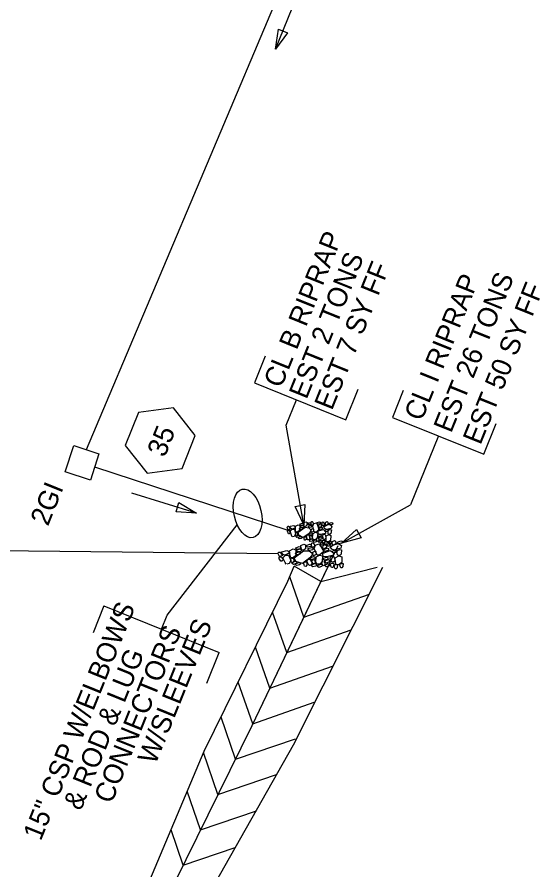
# Model space of a CAD drawing. Extents: x 2384780 to 2405432, y 547869 to 573706.
# Drawn here: x 2395530.7 to 2395662.9, y 556614.5 to 556830.4 of the extents above; entities that cross this region are included whole.
import ezdxf

# ---------------------------------------------------------------- set-up
doc = ezdxf.new("R2010")
doc.units = 0
for name, color, linetype in [('Old_Level_1', 7, 'Continuous'), ('Old_Level_10', 7, 'Continuous'), ('Old_Level_18', 7, 'Continuous'), ('Old_Level_20', 7, 'Continuous'), ('Old_Level_5', 7, 'Continuous'), ('Old_Level_9', 7, 'Continuous'), ('Prop Drainage Box Number Symbol CELL', 7, 'Continuous')]:
    doc.layers.add(name, color=color, linetype=linetype)

# ---------------------------------------------------------------- blocks, each defined once
blk = doc.blocks.new('BUBBLE')
at = {"layer": 'Old_Level_10'}
blk.add_ellipse((0, 0), major_axis=(192.5, 153.8), ratio=0.548538, dxfattribs=at)

msp = doc.modelspace()

# ---------------------------------------------------------------- linework, layer by layer
at = {"layer": 'Old_Level_1'}
for p, q in [((2395548.19, 556720.95), (2395656.03, 556976.14)), ((2395550.28, 556716.57), (2395599.15, 556700.58)), ((2395304.76, 556697.48), (2395596.66, 556694.68))]:
    msp.add_line(p, q, dxfattribs=at)
for points in [[(2395603.28, 556701.46), (2395603.18, 556701.86), (2395603.2, 556702.46), (2395603.72, 556702.67), (2395604.02, 556702.51), (2395603.9, 556701.65), (2395603.57, 556701.44), (2395603.28, 556701.46)], [(2395605.34, 556702.73), (2395605.52, 556702.54), (2395605.62, 556702.12), (2395605.41, 556701.83), (2395605.09, 556701.83), (2395605.04, 556702.44), (2395605.15, 556702.73), (2395605.34, 556702.73)], [(2395607.45, 556702.37), (2395607.26, 556702.14), (2395606.77, 556702.05), (2395606.54, 556702.27), (2395606.59, 556702.45), (2395607.15, 556702.63), (2395607.33, 556702.56), (2395607.45, 556702.37)], [(2395608.08, 556702.65), (2395608.29, 556702.37), (2395608.35, 556701.93), (2395608.16, 556701.66), (2395607.86, 556701.67), (2395607.81, 556702.27), (2395607.88, 556702.57), (2395608.08, 556702.65)], [(2395608.77, 556701.82), (2395608.67, 556702.12), (2395608.8, 556702.53), (2395609.14, 556702.7), (2395609.32, 556702.58), (2395609.3, 556701.98), (2395608.96, 556701.81), (2395608.77, 556701.82)], [(2395599.45, 556701.57), (2395599.53, 556701.34), (2395599.74, 556700.8), (2395599.43, 556700.67), (2395599.24, 556700.67), (2395599.02, 556701.24), (2395599.15, 556701.57), (2395599.45, 556701.57)], [(2395599.55, 556700.55), (2395599.61, 556700.33), (2395599.82, 556699.83), (2395599.52, 556699.65), (2395599.34, 556699.66), (2395599.08, 556700.28), (2395599.25, 556700.57), (2395599.55, 556700.55)], [(2395601.05, 556701.17), (2395600.74, 556701), (2395600.14, 556700.79), (2395599.73, 556701.15), (2395599.74, 556701.55), (2395600.65, 556701.72), (2395600.94, 556701.51), (2395601.05, 556701.17)], [(2395600.22, 556698.89), (2395600.05, 556699.3), (2395599.78, 556700.29), (2395600.29, 556700.8), (2395600.82, 556700.73), (2395601.07, 556699.53), (2395600.75, 556698.97), (2395600.34, 556698.88)], [(2395601.16, 556700.09), (2395601.06, 556700.58), (2395601.1, 556701.59), (2395601.79, 556701.92), (2395602.19, 556701.71), (2395602.07, 556700.47), (2395601.64, 556700.08), (2395601.16, 556700.09)], [(2395604.99, 556700.34), (2395604.48, 556699.65), (2395603.04, 556698.68), (2395601.97, 556699.24), (2395601.76, 556700.04), (2395603.52, 556701.3), (2395604.49, 556701.14), (2395605.13, 556700.44)], [(2395602.97, 556700.91), (2395602.79, 556700.7), (2395602.29, 556700.61), (2395602.07, 556700.82), (2395602.11, 556701.01), (2395602.69, 556701.19), (2395602.87, 556701.11), (2395602.97, 556700.91)], [(2395603.15, 556702.02), (2395602.96, 556701.79), (2395602.47, 556701.7), (2395602.24, 556701.93), (2395602.29, 556702.11), (2395602.86, 556702.28), (2395603.04, 556702.21), (2395603.15, 556702.02)], [(2395603.25, 556701.44), (2395603.02, 556701.22), (2395602.54, 556701.17), (2395602.31, 556701.36), (2395602.32, 556701.59), (2395602.97, 556701.75), (2395603.15, 556701.63), (2395603.25, 556701.44)], [(2395605.04, 556702.24), (2395604.84, 556702.02), (2395604.34, 556701.94), (2395604.13, 556702.15), (2395604.18, 556702.34), (2395604.74, 556702.52), (2395604.92, 556702.43), (2395605.04, 556702.24)], [(2395605.29, 556701.46), (2395605.1, 556701.27), (2395604.62, 556701.21), (2395604.39, 556701.41), (2395604.4, 556701.63), (2395605.01, 556701.78), (2395605.19, 556701.65), (2395605.29, 556701.46)], [(2395605.12, 556700.06), (2395605.01, 556700.36), (2395605.13, 556700.77), (2395605.48, 556700.95), (2395605.66, 556700.83), (2395605.64, 556700.23), (2395605.3, 556700.04), (2395605.12, 556700.06)], [(2395606.38, 556702.28), (2395606.63, 556701.8), (2395607.04, 556700.69), (2395606.31, 556700.08), (2395605.82, 556700.09), (2395605.45, 556701.53), (2395605.76, 556702.22), (2395606.37, 556702.4)], [(2395606.77, 556700.29), (2395607.18, 556700.45), (2395608.21, 556700.72), (2395608.67, 556700.22), (2395608.65, 556699.7), (2395607.45, 556699.48), (2395606.85, 556699.65), (2395606.8, 556700.18)], [(2395607.07, 556701.26), (2395606.97, 556701.57), (2395607.09, 556701.97), (2395607.44, 556702.16), (2395607.62, 556702.03), (2395607.6, 556701.43), (2395607.26, 556701.25), (2395607.07, 556701.26)], [(2395607.97, 556701), (2395607.8, 556700.82), (2395607.25, 556700.68), (2395607.04, 556700.91), (2395607.09, 556701.1), (2395607.69, 556701.3), (2395607.87, 556701.23), (2395607.97, 556701)], [(2395608.34, 556701.47), (2395608.75, 556701.76), (2395609.74, 556702.03), (2395610.26, 556701.52), (2395610.11, 556701.01), (2395608.91, 556700.73), (2395608.47, 556700.95), (2395608.26, 556701.47)], [(2395609.42, 556700.42), (2395609.22, 556700.2), (2395608.72, 556700.09), (2395608.51, 556700.33), (2395608.52, 556700.52), (2395609.13, 556700.72), (2395609.35, 556700.61), (2395609.42, 556700.42)], [(2395609.39, 556699.53), (2395609.34, 556699.9), (2395609.36, 556700.53), (2395609.9, 556700.72), (2395610.18, 556700.63), (2395610.04, 556699.7), (2395609.73, 556699.47), (2395609.39, 556699.53)], [(2395610.53, 556702.21), (2395610.34, 556701.98), (2395609.85, 556701.9), (2395609.62, 556702.12), (2395609.67, 556702.31), (2395610.23, 556702.49), (2395610.42, 556702.4), (2395610.53, 556702.21)], [(2395601.14, 556699.19), (2395601.14, 556699.41), (2395601.15, 556699.86), (2395601.46, 556699.97), (2395601.64, 556699.96), (2395601.62, 556699.36), (2395601.39, 556699.07), (2395601.14, 556699.19)], [(2395602.14, 556698.98), (2395601.95, 556698.77), (2395601.46, 556698.67), (2395601.25, 556698.9), (2395601.26, 556699.09), (2395601.86, 556699.28), (2395602.08, 556699.17), (2395602.14, 556698.98)], [(2395602.77, 556698.63), (2395602.54, 556698.45), (2395602.04, 556698.35), (2395601.83, 556698.55), (2395601.84, 556698.77), (2395602.48, 556698.94), (2395602.67, 556698.83), (2395602.77, 556698.63)], [(2395603.36, 556698.01), (2395603.29, 556698.32), (2395603.27, 556698.81), (2395603.61, 556698.9), (2395603.87, 556698.82), (2395603.77, 556698.19), (2395603.55, 556697.98), (2395603.36, 556698.01)], [(2395604.23, 556698.09), (2395604.02, 556698.39), (2395603.85, 556699.07), (2395604.17, 556699.39), (2395604.47, 556699.38), (2395604.75, 556698.55), (2395604.54, 556698.17), (2395604.23, 556698.09)], [(2395605.41, 556699.54), (2395605.24, 556699.32), (2395604.73, 556699.26), (2395604.52, 556699.45), (2395604.53, 556699.67), (2395605.13, 556699.85), (2395605.35, 556699.73), (2395605.41, 556699.54)], [(2395605.49, 556698.02), (2395605.31, 556697.8), (2395604.81, 556697.71), (2395604.6, 556697.94), (2395604.61, 556698.13), (2395605.21, 556698.33), (2395605.43, 556698.21), (2395605.49, 556698.02)], [(2395605.14, 556699.19), (2395605.24, 556698.97), (2395605.43, 556698.47), (2395605.09, 556698.29), (2395604.93, 556698.3), (2395604.73, 556698.91), (2395604.84, 556699.09), (2395605.14, 556699.19)], [(2395605.53, 556698.18), (2395605.44, 556698.71), (2395605.57, 556699.72), (2395606.19, 556700), (2395606.71, 556699.8), (2395606.56, 556698.61), (2395606.05, 556698.1), (2395605.53, 556698.18)], [(2395606.85, 556698.64), (2395606.92, 556698.43), (2395607, 556697.94), (2395606.78, 556697.72), (2395606.63, 556697.72), (2395606.42, 556698.22), (2395606.55, 556698.51), (2395606.74, 556698.61)], [(2395607.66, 556699.13), (2395607.43, 556698.9), (2395606.94, 556698.82), (2395606.73, 556699.05), (2395606.76, 556699.24), (2395607.33, 556699.41), (2395607.55, 556699.32), (2395607.66, 556699.13)], [(2395607.94, 556698.41), (2395607.75, 556698.34), (2395607.25, 556698.16), (2395607.03, 556698.47), (2395607.04, 556698.66), (2395607.69, 556698.86), (2395607.84, 556698.64), (2395607.94, 556698.41)], [(2395608.54, 556699.55), (2395608.71, 556699.21), (2395608.81, 556698.49), (2395608.49, 556698.2), (2395608.19, 556698.22), (2395608, 556699.04), (2395608.12, 556699.41), (2395608.54, 556699.55)], [(2395608.92, 556697.59), (2395608.86, 556698.11), (2395608.87, 556699.08), (2395609.59, 556699.41), (2395610.06, 556699.17), (2395609.95, 556697.97), (2395609.45, 556697.57), (2395608.92, 556697.59)], [(2395602.46, 556696.13), (2395602.23, 556695.83), (2395601.54, 556695.65), (2395601.18, 556695.88), (2395601.22, 556696.11), (2395602.01, 556696.4), (2395602.29, 556696.35), (2395602.46, 556696.13)], [(2395602.74, 556695.49), (2395602.53, 556695.96), (2395602.47, 556696.67), (2395603.18, 556697), (2395603.64, 556696.85), (2395603.6, 556695.81), (2395603.15, 556695.51), (2395602.74, 556695.49)], [(2395605.13, 556696.69), (2395604.88, 556696.41), (2395604.19, 556696.23), (2395603.85, 556696.45), (2395603.89, 556696.67), (2395604.66, 556696.98), (2395604.94, 556696.91), (2395605.13, 556696.69)], [(2395605.62, 556695.81), (2395605.37, 556695.55), (2395604.69, 556695.4), (2395604.34, 556695.6), (2395604.32, 556695.87), (2395605.17, 556696.14), (2395605.45, 556696.02), (2395605.62, 556695.81)], [(2395605.49, 556697.33), (2395605.77, 556697.12), (2395605.98, 556696.64), (2395605.74, 556696.27), (2395605.27, 556696.22), (2395605.1, 556696.93), (2395605.22, 556697.3), (2395605.49, 556697.33)], [(2395606.51, 556697.78), (2395606.32, 556697.56), (2395605.82, 556697.46), (2395605.61, 556697.7), (2395605.62, 556697.89), (2395606.22, 556698.09), (2395606.44, 556697.97), (2395606.51, 556697.78)], [(2395607.05, 556696.95), (2395607.48, 556696.42), (2395608.24, 556695.16), (2395607.29, 556694.32), (2395606.59, 556694.26), (2395605.83, 556695.91), (2395606.17, 556696.79), (2395607.02, 556697.1)], [(2395607.88, 556697.7), (2395607.6, 556697.51), (2395607.11, 556697.39), (2395606.94, 556697.63), (2395606.94, 556697.8), (2395607.56, 556698.02), (2395607.78, 556697.89), (2395607.88, 556697.7)], [(2395608.56, 556697.23), (2395608.33, 556696.93), (2395607.64, 556696.75), (2395607.28, 556696.97), (2395607.32, 556697.19), (2395608.09, 556697.5), (2395608.37, 556697.44), (2395608.56, 556697.23)], [(2395608.02, 556697.13), (2395607.94, 556697.43), (2395607.92, 556697.92), (2395608.26, 556698.02), (2395608.52, 556697.94), (2395608.42, 556697.31), (2395608.2, 556697.09), (2395608.02, 556697.13)], [(2395608.2, 556695.85), (2395608, 556696.2), (2395608.11, 556696.7), (2395608.58, 556696.97), (2395608.86, 556696.86), (2395608.92, 556696.14), (2395608.47, 556695.87), (2395608.2, 556695.85)], [(2395608.62, 556696.78), (2395608.55, 556697.09), (2395608.52, 556697.58), (2395608.87, 556697.67), (2395609.12, 556697.59), (2395609.03, 556696.96), (2395608.8, 556696.75), (2395608.62, 556696.78)], [(2395609.42, 556697.66), (2395609.76, 556697.36), (2395609.92, 556696.85), (2395609.69, 556696.5), (2395609.26, 556696.46), (2395609.09, 556697.17), (2395609.16, 556697.54), (2395609.42, 556697.66)], [(2395609.62, 556696.89), (2395609.55, 556697.19), (2395609.53, 556697.68), (2395609.87, 556697.78), (2395610.13, 556697.7), (2395610.03, 556697.07), (2395609.81, 556696.85), (2395609.62, 556696.89)], [(2395609.97, 556696.3), (2395610.53, 556696.71), (2395611.9, 556697.19), (2395612.71, 556696.67), (2395612.59, 556696.03), (2395610.91, 556695.51), (2395610.25, 556695.7), (2395609.87, 556696.29)], [(2395610.54, 556696.78), (2395610.35, 556697.13), (2395610.47, 556697.64), (2395610.94, 556697.89), (2395611.21, 556697.77), (2395611.28, 556697.06), (2395610.81, 556696.8), (2395610.54, 556696.78)], [(2395613, 556697.53), (2395612.76, 556697.23), (2395612.07, 556697.05), (2395611.72, 556697.28), (2395611.75, 556697.51), (2395612.53, 556697.81), (2395612.8, 556697.74), (2395613, 556697.53)], [(2395597.25, 556695.02), (2395597.39, 556694.76), (2395597.77, 556694.15), (2395597.35, 556693.94), (2395597.09, 556693.91), (2395596.68, 556694.56), (2395596.82, 556694.97), (2395597.25, 556695.02)], [(2395599.59, 556694.79), (2395599.17, 556694.54), (2395598.35, 556694.2), (2395597.71, 556694.57), (2395597.66, 556695.04), (2395598.94, 556695.38), (2395599.39, 556695.18), (2395599.59, 556694.79)], [(2395598.76, 556691.94), (2395598.46, 556692.4), (2395597.92, 556693.54), (2395598.56, 556694.23), (2395599.34, 556694.23), (2395599.88, 556692.84), (2395599.51, 556692.12), (2395598.94, 556691.95)], [(2395599.93, 556693.52), (2395599.71, 556694.09), (2395599.59, 556695.3), (2395600.54, 556695.8), (2395601.14, 556695.61), (2395601.17, 556694.12), (2395600.61, 556693.59), (2395599.93, 556693.52)], [(2395605.37, 556694.42), (2395604.74, 556693.53), (2395602.83, 556692.14), (2395601.21, 556692.64), (2395600.79, 556693.56), (2395603.11, 556695.33), (2395604.52, 556695.3), (2395605.54, 556694.57)], [(2395602.39, 556694.79), (2395602.15, 556694.5), (2395601.46, 556694.32), (2395601.1, 556694.54), (2395601.14, 556694.77), (2395601.94, 556695.08), (2395602.21, 556695), (2395602.39, 556694.79)], [(2395602.71, 556695.46), (2395602.4, 556695.17), (2395601.72, 556695.03), (2395601.37, 556695.22), (2395601.35, 556695.49), (2395602.25, 556695.79), (2395602.53, 556695.67), (2395602.71, 556695.46)], [(2395605.59, 556694.11), (2395605.38, 556694.45), (2395605.5, 556694.96), (2395605.97, 556695.23), (2395606.24, 556695.11), (2395606.31, 556694.39), (2395605.86, 556694.12), (2395605.59, 556694.11)], [(2395606.47, 556691.94), (2395606.26, 556692.56), (2395606.29, 556693.78), (2395607.13, 556694.21), (2395607.9, 556694.06), (2395607.88, 556692.61), (2395607.22, 556691.93), (2395606.47, 556691.94)], [(2395607.92, 556694.65), (2395608.48, 556694.91), (2395609.91, 556695.39), (2395610.64, 556694.87), (2395610.7, 556694.24), (2395609.02, 556693.78), (2395608.13, 556693.89), (2395607.98, 556694.52)], [(2395609.53, 556695.68), (2395609.31, 556695.44), (2395608.55, 556695.18), (2395608.21, 556695.43), (2395608.25, 556695.66), (2395609.07, 556696), (2395609.35, 556695.94), (2395609.53, 556695.68)], [(2395610.57, 556694.05), (2395610.86, 556693.66), (2395611.12, 556692.82), (2395610.71, 556692.44), (2395610.28, 556692.41), (2395609.87, 556693.36), (2395609.99, 556693.82), (2395610.57, 556694.05)], [(2395611.68, 556695.22), (2395611.43, 556694.93), (2395610.74, 556694.72), (2395610.4, 556694.97), (2395610.39, 556695.2), (2395611.23, 556695.53), (2395611.56, 556695.44), (2395611.68, 556695.22)], [(2395611.42, 556691.77), (2395611.25, 556692.38), (2395611.11, 556693.54), (2395612.08, 556694.04), (2395612.8, 556693.83), (2395612.82, 556692.39), (2395612.17, 556691.84), (2395611.42, 556691.77)], [(2395611.79, 556694.16), (2395611.65, 556694.58), (2395611.59, 556695.35), (2395612.32, 556695.65), (2395612.74, 556695.59), (2395612.69, 556694.46), (2395612.28, 556694.14), (2395611.79, 556694.16)], [(2395597.54, 556693.82), (2395597.67, 556693.57), (2395598.05, 556693.01), (2395597.65, 556692.74), (2395597.38, 556692.73), (2395596.92, 556693.42), (2395597.11, 556693.79), (2395597.54, 556693.82)], [(2395600.03, 556692.44), (2395599.99, 556692.71), (2395599.94, 556693.25), (2395600.36, 556693.43), (2395600.63, 556693.44), (2395600.7, 556692.73), (2395600.41, 556692.35), (2395600.03, 556692.44)], [(2395601.5, 556692.36), (2395601.26, 556692.07), (2395600.57, 556691.88), (2395600.23, 556692.13), (2395600.22, 556692.35), (2395601.04, 556692.67), (2395601.37, 556692.57), (2395601.5, 556692.36)], [(2395602.45, 556692.04), (2395602.15, 556691.78), (2395601.46, 556691.59), (2395601.12, 556691.79), (2395601.1, 556692.06), (2395601.98, 556692.36), (2395602.28, 556692.26), (2395602.45, 556692.04)], [(2395603.4, 556691.4), (2395603.25, 556691.75), (2395603.14, 556692.33), (2395603.62, 556692.49), (2395604, 556692.44), (2395603.96, 556691.67), (2395603.67, 556691.38), (2395603.4, 556691.4)], [(2395604.63, 556691.63), (2395604.28, 556691.95), (2395603.93, 556692.74), (2395604.33, 556693.17), (2395604.76, 556693.2), (2395605.29, 556692.25), (2395605.05, 556691.77), (2395604.63, 556691.63)], [(2395606.09, 556693.54), (2395605.88, 556693.25), (2395605.16, 556693.1), (2395604.83, 556693.29), (2395604.81, 556693.56), (2395605.64, 556693.87), (2395605.97, 556693.76), (2395606.09, 556693.54)], [(2395606.44, 556691.74), (2395606.21, 556691.46), (2395605.52, 556691.26), (2395605.18, 556691.51), (2395605.16, 556691.73), (2395605.99, 556692.07), (2395606.32, 556691.96), (2395606.44, 556691.74)], [(2395605.76, 556693.08), (2395605.94, 556692.84), (2395606.28, 556692.27), (2395605.83, 556692), (2395605.6, 556691.99), (2395605.21, 556692.68), (2395605.34, 556692.92), (2395605.76, 556693.08)], [(2395607.93, 556691.61), (2395607.69, 556691.33), (2395607, 556691.13), (2395606.66, 556691.38), (2395606.65, 556691.6), (2395607.48, 556691.94), (2395607.81, 556691.83), (2395607.93, 556691.61)], [(2395608.29, 556692.7), (2395608.42, 556692.45), (2395608.62, 556691.88), (2395608.33, 556691.59), (2395608.11, 556691.56), (2395607.73, 556692.12), (2395607.87, 556692.49), (2395608.13, 556692.65)], [(2395609.37, 556693.4), (2395609.08, 556693.1), (2395608.39, 556692.92), (2395608.05, 556693.17), (2395608.07, 556693.39), (2395608.86, 556693.68), (2395609.19, 556693.62), (2395609.37, 556693.4)], [(2395609.91, 556691.74), (2395609.54, 556691.47), (2395608.85, 556691.25), (2395608.57, 556691.5), (2395608.55, 556691.71), (2395609.4, 556692.07), (2395609.73, 556691.95), (2395609.91, 556691.74)], [(2395609.89, 556692.59), (2395609.62, 556692.49), (2395608.94, 556692.19), (2395608.57, 556692.52), (2395608.56, 556692.75), (2395609.46, 556693.09), (2395609.71, 556692.85), (2395609.89, 556692.59)], [(2395610.2, 556691.08), (2395610.03, 556691.43), (2395609.92, 556692.01), (2395610.4, 556692.17), (2395610.78, 556692.12), (2395610.74, 556691.35), (2395610.45, 556691.07), (2395610.2, 556691.08)], [(2395611.1, 556690.76), (2395610.96, 556691.11), (2395610.85, 556691.69), (2395611.32, 556691.86), (2395611.7, 556691.81), (2395611.66, 556691.04), (2395611.38, 556690.75), (2395611.1, 556690.76)], [(2395612.53, 556691.05), (2395612.38, 556691.4), (2395612.27, 556691.98), (2395612.75, 556692.14), (2395613.13, 556692.09), (2395613.09, 556691.32), (2395612.8, 556691.04), (2395612.53, 556691.05)]]:
    msp.add_lwpolyline(points, dxfattribs=at)
at = {"layer": 'Old_Level_18'}
for p, q in [((2395612.76, 556697.22), (2395630.18, 556706.94)), ((2395607.54, 556687.54), (2395600.79, 556691.46)), ((2395607.54, 556687.54), (2395621.72, 556691.19)), ((2395603.22, 556678.54), (2395599.64, 556688.71)), ((2395603.22, 556678.54), (2395619.78, 556684.37)), ((2395598.91, 556669.54), (2395595.31, 556679.75)), ((2395598.91, 556669.54), (2395615.2, 556675.28)), ((2395594.6, 556660.54), (2395590.95, 556670.9)), ((2395594.6, 556660.54), (2395610.44, 556666.12)), ((2395590.29, 556651.54), (2395586.59, 556662.04)), ((2395590.29, 556651.54), (2395605.81, 556657.01)), ((2395585.89, 556642.58), (2395582.25, 556653.24)), ((2395585.89, 556642.58), (2395601.12, 556647.77)), ((2395581.48, 556633.62), (2395577.85, 556644.29)), ((2395581.48, 556633.62), (2395596.31, 556638.68)), ((2395577.08, 556624.67), (2395573.73, 556634.48)), ((2395577.08, 556624.67), (2395591.21, 556629.48)), ((2395572.67, 556615.71), (2395569.61, 556624.69)), ((2395572.67, 556615.71), (2395585.83, 556620.19))]:
    msp.add_line(p, q, dxfattribs=at)
msp.add_lwpolyline([(2395617.74, 556698.57), (2395612.76, 556697.22), (2395616.52, 556700.75)], close=True, dxfattribs=at)
for points in [[(2395611.85, 556696.54), (2395590.06, 556651.06), (2395570.57, 556611.44), (2395554.48, 556569.6), (2395542.38, 556520.86)], [(2395540.65, 556523.73), (2395548.23, 556565.15), (2395562.9, 556608.75), (2395577.98, 556644.57), (2395599.18, 556687.6), (2395600.79, 556691.46)], [(2395609.38, 556691.4), (2395590.06, 556651.06), (2395570.57, 556611.44), (2395554.48, 556569.6), (2395542.38, 556520.86)], [(2395544.64, 556523.22), (2395560.16, 556566.04), (2395579.3, 556608.68), (2395600.57, 556646.2), (2395623.19, 556691.16)]]:
    msp.add_lwpolyline(points, dxfattribs=at)
at = {"layer": 'Old_Level_20'}
for p, q in [((2395637.24, 556724.4), (2395630.18, 556706.94)), ((2395552.64, 556681.36), (2395549.9, 556674.57)), ((2395552.64, 556681.36), (2395581.8, 556669.58)), ((2395578.66, 556661.82), (2395581.8, 556669.58))]:
    msp.add_line(p, q, dxfattribs=at)
for points in [[(2395593.44, 556744.63), (2395590.69, 556737.84), (2395613.83, 556728.49), (2395616.97, 556736.26)], [(2395628.34, 556735.89), (2395625.6, 556729.1), (2395648.74, 556719.75), (2395651.87, 556727.51)]]:
    msp.add_lwpolyline(points, dxfattribs=at)
at = {"layer": 'Old_Level_5'}
for p, q in [((2395596.06, 556822.28), (2395601.98, 556836.92)), ((2395598.75, 556727.13), (2395601.34, 556733.54)), ((2395603.18, 556701.86), (2395598.75, 556727.13)), ((2395576.02, 556704.87), (2395559.69, 556709.94)), ((2395568.65, 556679.03), (2395586.35, 556701.9)), ((2395567.22, 556675.47), (2395568.65, 556679.03))]:
    msp.add_line(p, q, dxfattribs=at)
for points in [[(2395599.09, 556826.44), (2395596.06, 556822.28), (2395596.77, 556827.38)], [(2395571.62, 556707.54), (2395576.02, 556704.87), (2395570.88, 556705.16)], [(2395603.47, 556707.01), (2395603.18, 556701.86), (2395601.01, 556706.54)]]:
    msp.add_lwpolyline(points, close=True, dxfattribs=at)
at = {"layer": 'Old_Level_9'}
msp.add_lwpolyline([(2395542.82, 556715.31), (2395545, 556721.99), (2395551.38, 556719.9), (2395549.19, 556713.24)], close=True, dxfattribs=at)
at = {"layer": 'Prop Drainage Box Number Symbol CELL'}
msp.add_lwpolyline([(2395570.23, 556731.54), (2395561.37, 556730.3), (2395558.02, 556722), (2395563.53, 556714.95), (2395572.39, 556716.19), (2395575.74, 556724.49)], close=True, dxfattribs=at)

# ---------------------------------------------------------------- block references
at = {"layer": 'Old_Level_5', "xscale": 0.025500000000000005, "yscale": 0.025500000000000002, "rotation": 63.95141885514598}
msp.add_blockref('BUBBLE', (2395589, 556704.8), dxfattribs=at)

# ---------------------------------------------------------------- texts
at = {"layer": 'Old_Level_5'}
for s, p in [('CL B RIPRAP', (2395597.49, 556736.3)), ('EST 2 TONS', (2395603.89, 556733.46)), ('EST 7 SY FF', (2395610.31, 556730.66)), ('CL I RIPRAP', (2395633.05, 556727.91)), ('EST 26 TONS', (2395640.47, 556724.92)), ('EST 50 SY FF', (2395647.89, 556721.92)), ('2GI', (2395538.47, 556701.38)), ('15" CSP W/ELBOWS', (2395536.64, 556621.7)), ('W/SLEEVES', (2395565.64, 556640.97)), ('CONNECTORS', (2395554.57, 556631.07)), ('& ROD & LUG', (2395546.8, 556629.35))]:
    msp.add_text(s, height=5, rotation=68.0001, dxfattribs=at).set_placement(p)
at = {"layer": 'Prop Drainage Box Number Symbol CELL'}
msp.add_text('35', height=5, rotation=68.0001, dxfattribs=at).set_placement((2395568.02, 556718.77))

doc.saveas('drawing.dxf')
